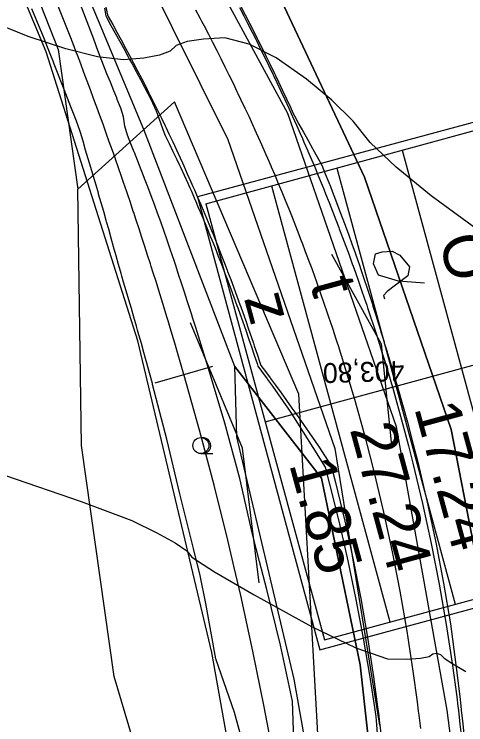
# Model space of a CAD drawing. Extents: x -574342 to -508101, y -1143544 to -1123894.
# Drawn here: x -508528.83 to -508506.16, y -1143313.1 to -1143277.46 of the extents above; entities that cross this region are included whole.
import ezdxf

# ---------------------------------------------------------------- set-up
doc = ezdxf.new("R2010")
doc.units = 0
for name, color, linetype in [('01_PARCELY_NAVRH_PC', 7, 'Continuous'), ('01_PARCELY_NAVRH_VHO', 7, 'Continuous'), ('01_PARCELY_NAVRH_ŽP', 7, 'Continuous'), ('1000', 7, 'Continuous'), ('21', 7, 'Continuous'), ('37', 7, 'Continuous'), ('42', 7, 'Continuous'), ('43', 7, 'Continuous'), ('6', 7, 'Continuous'), ('Level 255', 7, 'Continuous'), ('SO 101_popis oblouku', 7, 'Continuous'), ('tab', 7, 'Continuous'), ('VRST VEDL', 7, 'Continuous')]:
    doc.layers.add(name, color=color, linetype=linetype)

msp = doc.modelspace()

# ---------------------------------------------------------------- linework, layer by layer
msp.add_lwpolyline([(-508519.625, -1143286.627), (-508513.495, -1143309.334), (-508492.475, -1143303.66), (-508498.604, -1143280.952)], close=True)
at = {"layer": '01_PARCELY_NAVRH_PC'}
for points in [[(-508491.36, -1143454.58), (-508498.26, -1143372.94), (-508504.21, -1143312.1), (-508506.89, -1143298.29), (-508511.25, -1143285.64), (-508519.86, -1143267.33), (-508524.26, -1143263.08), (-508531.16, -1143250.06)], [(-508491.36, -1143454.58), (-508498.26, -1143372.94), (-508504.21, -1143312.1), (-508506.89, -1143298.29), (-508511.25, -1143285.64), (-508519.86, -1143267.33), (-508524.26, -1143263.08), (-508531.16, -1143250.06)], [(-508534.5, -1143254.93), (-508531.94, -1143260.32), (-508524.61, -1143277.77), (-508522.34, -1143283.22), (-508517.78, -1143295.12), (-508513.41, -1143300.73), (-508511.47, -1143310.09), (-508503.21, -1143384.65), (-508499.31, -1143428.14)], [(-508534.5, -1143254.93), (-508531.94, -1143260.32), (-508524.61, -1143277.77), (-508522.34, -1143283.22), (-508517.78, -1143295.12), (-508513.41, -1143300.73), (-508511.47, -1143310.09), (-508503.21, -1143384.65), (-508499.31, -1143428.14)]]:
    msp.add_lwpolyline(points, dxfattribs=at)
at = {"layer": '01_PARCELY_NAVRH_VHO'}
msp.add_lwpolyline([(-508497.13, -1143495.86), (-508497.34, -1143500.64), (-508499.94, -1143496.07), (-508501.52, -1143472.9), (-508509.71, -1143373.98), (-508513.61, -1143343.97), (-508516.21, -1143324.53), (-508518.91, -1143309.47), (-508522.63, -1143293.85), (-508527.23, -1143279.34), (-508534.32, -1143262.4), (-508535.36, -1143259.89), (-508531.94, -1143260.32), (-508524.61, -1143277.77), (-508522.34, -1143283.22), (-508517.78, -1143295.12), (-508517.67, -1143298.65), (-508514.79, -1143310.81), (-508512.2, -1143325.42), (-508505.85, -1143384.53), (-508502.4, -1143424.77), (-508500.25, -1143457.08), (-508499.28, -1143468.17)], close=True, dxfattribs=at)
msp.add_lwpolyline([(-508497.13, -1143495.86), (-508497.34, -1143500.64), (-508499.94, -1143496.07), (-508501.52, -1143472.9), (-508509.71, -1143373.98), (-508513.61, -1143343.97), (-508516.21, -1143324.53), (-508518.91, -1143309.47), (-508522.63, -1143293.85), (-508527.23, -1143279.34), (-508534.32, -1143262.4), (-508535.36, -1143259.89), (-508531.94, -1143260.32), (-508524.61, -1143277.77), (-508522.34, -1143283.22), (-508517.78, -1143295.12), (-508517.67, -1143298.65), (-508514.79, -1143310.81), (-508512.2, -1143325.42), (-508505.85, -1143384.53), (-508502.4, -1143424.77), (-508500.25, -1143457.08), (-508499.28, -1143468.17)], close=True, dxfattribs=at)
at = {"layer": '01_PARCELY_NAVRH_ŽP'}
for points in [[(-508425.23, -1143400.39), (-508448.26, -1143343.08), (-508432.21, -1143324.29), (-508434.31, -1143320.59), (-508441.9, -1143297.61), (-508445.4, -1143275.01), (-508446.02, -1143260.22), (-508475.11, -1143263.39), (-508493.5, -1143263.3), (-508514.56, -1143259.91), (-508521.01, -1143259.29), (-508524.26, -1143263.08), (-508519.86, -1143267.33), (-508511.25, -1143285.64), (-508506.89, -1143298.29), (-508504.21, -1143312.1), (-508498.26, -1143372.94), (-508491.36, -1143454.58)], [(-508493.822, -1143536.058), (-508493.49, -1143517.55), (-508493.74, -1143496.02), (-508496.01, -1143459.9), (-508497.29, -1143445.8), (-508499.31, -1143428.14), (-508503.21, -1143384.65), (-508511.47, -1143310.09), (-508513.41, -1143300.73), (-508517.78, -1143295.12), (-508517.67, -1143298.65), (-508514.79, -1143310.81), (-508512.2, -1143325.42), (-508505.85, -1143384.53), (-508502.4, -1143424.77), (-508500.25, -1143457.08), (-508499.28, -1143468.17), (-508497.13, -1143495.86), (-508497.34, -1143500.64), (-508498.93, -1143536.058)]]:
    msp.add_lwpolyline(points, dxfattribs=at)
at = {"layer": '1000'}
for points in [[(-508514.755, -1143314.812), (-508514.869, -1143311.915), (-508515.463, -1143309.107), (-508516.152, -1143306.32), (-508516.515, -1143304.909), (-508516.875, -1143303.544), (-508517.501, -1143300.743), (-508518.265, -1143297.978), (-508519.083, -1143295.228), (-508519.097, -1143295.183), (-508519.581, -1143293.612), (-508519.72, -1143293.168), (-508519.86, -1143292.725), (-508519.934, -1143292.49), (-508520.001, -1143292.281), (-508520.143, -1143291.838), (-508520.287, -1143291.396), (-508520.431, -1143290.954), (-508520.576, -1143290.512), (-508520.723, -1143290.071), (-508520.825, -1143289.765), (-508520.871, -1143289.63), (-508521.019, -1143289.189), (-508521.169, -1143288.749), (-508521.32, -1143288.309), (-508521.472, -1143287.869), (-508521.631, -1143287.432), (-508521.771, -1143287.058), (-508521.795, -1143286.997), (-508521.959, -1143286.562), (-508522.125, -1143286.127), (-508522.292, -1143285.693), (-508522.309, -1143285.65), (-508522.46, -1143285.259), (-508522.629, -1143284.826), (-508522.799, -1143284.393), (-508522.803, -1143284.383), (-508522.97, -1143283.961), (-508523.142, -1143283.529), (-508523.272, -1143283.082), (-508523.343, -1143282.614), (-508523.483, -1143282.17), (-508523.654, -1143281.738), (-508523.687, -1143281.657), (-508523.827, -1143281.306), (-508524.001, -1143280.875), (-508524.176, -1143280.444), (-508524.352, -1143280.014), (-508524.516, -1143279.579), (-508524.676, -1143279.142), (-508524.733, -1143278.989), (-508524.838, -1143278.707), (-508525.001, -1143278.271), (-508525.164, -1143277.836), (-508525.748, -1143276.31)], [(-508517.023, -1143315.225), (-508517.78, -1143312.488), (-508518.703, -1143309.793), (-508519.215, -1143307.014), (-508519.493, -1143305.606), (-508519.837, -1143304.259), (-508520.512, -1143301.516), (-508521.176, -1143298.77), (-508521.884, -1143296.033), (-508521.897, -1143295.988), (-508522.323, -1143294.425), (-508522.447, -1143293.983), (-508522.571, -1143293.542), (-508522.637, -1143293.308), (-508522.696, -1143293.101), (-508522.823, -1143292.66), (-508522.95, -1143292.219), (-508523.078, -1143291.779), (-508523.207, -1143291.338), (-508523.338, -1143290.899), (-508523.429, -1143290.593), (-508523.469, -1143290.459), (-508523.599, -1143290.019), (-508523.72, -1143289.576), (-508523.842, -1143289.133), (-508523.965, -1143288.69), (-508524.088, -1143288.248), (-508524.195, -1143287.868), (-508524.213, -1143287.806), (-508524.339, -1143287.364), (-508524.465, -1143286.922), (-508524.592, -1143286.48), (-508524.605, -1143286.437), (-508524.721, -1143286.039), (-508524.85, -1143285.598), (-508524.98, -1143285.157), (-508524.983, -1143285.146), (-508525.111, -1143284.716), (-508525.244, -1143284.275), (-508525.377, -1143283.835), (-508525.51, -1143283.395), (-508525.661, -1143282.961), (-508525.819, -1143282.529), (-508525.85, -1143282.449), (-508525.984, -1143282.1), (-508526.15, -1143281.672), (-508526.317, -1143281.243), (-508526.484, -1143280.816), (-508526.653, -1143280.388), (-508526.822, -1143279.961), (-508526.882, -1143279.811), (-508526.992, -1143279.534), (-508527.163, -1143279.108), (-508527.335, -1143278.682), (-508527.948, -1143277.187)], [(-508524.306, -1143277.155), (-508524.234, -1143277.541), (-508524.193, -1143277.617), (-508523.973, -1143278.021), (-508523.972, -1143278.023), (-508523.765, -1143278.409), (-508523.55, -1143278.794), (-508523.336, -1143279.18), (-508523.124, -1143279.566), (-508523.037, -1143279.726), (-508522.914, -1143279.953), (-508522.705, -1143280.341), (-508522.498, -1143280.731), (-508522.293, -1143281.121), (-508522.126, -1143281.443), (-508522.09, -1143281.512), (-508521.889, -1143281.904), (-508521.712, -1143282.309), (-508521.559, -1143282.724), (-508521.408, -1143283.14), (-508521.373, -1143283.238), (-508521.248, -1143283.552), (-508521.055, -1143283.947), (-508520.864, -1143284.344), (-508520.674, -1143284.742), (-508520.554, -1143284.998), (-508520.487, -1143285.14), (-508520.301, -1143285.539), (-508520.117, -1143285.939), (-508520.014, -1143286.17), (-508519.939, -1143286.342), (-508519.763, -1143286.746), (-508519.754, -1143286.767), (-508519.59, -1143287.15), (-508519.418, -1143287.556), (-508519.248, -1143287.962), (-508519.08, -1143288.369), (-508519.003, -1143288.558), (-508518.914, -1143288.777), (-508518.749, -1143289.185), (-508518.586, -1143289.594), (-508518.426, -1143290.004), (-508518.287, -1143290.363), (-508518.267, -1143290.415), (-508518.11, -1143290.826), (-508517.954, -1143291.239), (-508517.801, -1143291.651), (-508517.649, -1143292.065), (-508517.607, -1143292.182), (-508517.5, -1143292.479), (-508517.352, -1143292.894), (-508517.206, -1143293.309), (-508517.062, -1143293.726), (-508516.963, -1143294.014), (-508516.92, -1143294.142), (-508516.779, -1143294.56), (-508516.641, -1143294.978), (-508516.595, -1143295.119), (-508516.412, -1143295.367), (-508516.137, -1143295.743), (-508516.109, -1143295.781), (-508515.863, -1143296.12), (-508515.591, -1143296.5), (-508515.321, -1143296.881), (-508515.054, -1143297.265), (-508514.925, -1143297.464), (-508514.803, -1143297.655), (-508513.835, -1143299.2), (-508513.221, -1143300.185), (-508513, -1143301.025), (-508512.523, -1143302.946), (-508512.081, -1143304.876), (-508511.676, -1143306.815), (-508511.308, -1143308.761), (-508510.976, -1143310.715), (-508510.746, -1143312.227), (-508510.682, -1143312.676), (-508510.653, -1143312.879), (-508510.61, -1143313.536)], [(-508524.226, -1143277.11), (-508524.153, -1143277.496), (-508524.111, -1143277.572), (-508523.888, -1143277.973), (-508523.887, -1143277.975), (-508523.674, -1143278.36), (-508523.463, -1143278.747), (-508523.253, -1143279.135), (-508523.045, -1143279.524), (-508522.959, -1143279.685), (-508522.838, -1143279.913), (-508522.634, -1143280.304), (-508522.431, -1143280.696), (-508522.23, -1143281.089), (-508522.066, -1143281.413), (-508522.031, -1143281.482), (-508521.834, -1143281.877), (-508521.639, -1143282.272), (-508521.445, -1143282.669), (-508521.253, -1143283.066), (-508521.209, -1143283.159), (-508521.063, -1143283.464), (-508520.875, -1143283.863), (-508520.689, -1143284.263), (-508520.504, -1143284.664), (-508520.386, -1143284.922), (-508520.322, -1143285.065), (-508520.141, -1143285.467), (-508519.962, -1143285.871), (-508519.86, -1143286.103), (-508519.785, -1143286.275), (-508519.61, -1143286.679), (-508519.6, -1143286.701), (-508519.436, -1143287.085), (-508519.265, -1143287.492), (-508519.095, -1143287.899), (-508518.927, -1143288.307), (-508518.85, -1143288.496), (-508518.762, -1143288.715), (-508518.598, -1143289.125), (-508518.435, -1143289.535), (-508518.275, -1143289.946), (-508518.137, -1143290.305), (-508518.117, -1143290.358), (-508517.96, -1143290.77), (-508517.806, -1143291.183), (-508517.653, -1143291.597), (-508517.503, -1143292.012), (-508517.46, -1143292.129), (-508517.354, -1143292.427), (-508517.207, -1143292.843), (-508517.062, -1143293.26), (-508516.919, -1143293.677), (-508516.821, -1143293.966), (-508516.777, -1143294.095), (-508516.638, -1143294.513), (-508516.501, -1143294.932), (-508516.455, -1143295.074), (-508516.269, -1143295.321), (-508515.989, -1143295.696), (-508515.961, -1143295.735), (-508515.711, -1143296.073), (-508515.434, -1143296.452), (-508515.159, -1143296.833), (-508514.886, -1143297.215), (-508514.746, -1143297.412), (-508514.614, -1143297.6), (-508513.562, -1143299.126), (-508512.912, -1143300.105), (-508512.698, -1143300.949), (-508512.238, -1143302.881), (-508511.817, -1143304.821), (-508511.436, -1143306.77), (-508511.094, -1143308.726), (-508510.792, -1143310.689), (-508510.586, -1143312.207), (-508510.53, -1143312.657), (-508510.505, -1143312.861), (-508510.428, -1143313.516)], [(-508517.528, -1143277.12), (-508517.311, -1143277.535), (-508517.096, -1143277.951), (-508516.882, -1143278.369), (-508516.708, -1143278.713), (-508516.671, -1143278.787), (-508516.461, -1143279.206), (-508516.254, -1143279.626), (-508516.048, -1143280.047), (-508515.844, -1143280.47), (-508515.797, -1143280.568), (-508515.642, -1143280.892), (-508515.442, -1143281.316), (-508515.244, -1143281.741), (-508515.048, -1143282.167), (-508514.923, -1143282.441), (-508514.854, -1143282.594), (-508514.662, -1143283.021), (-508514.472, -1143283.449), (-508514.364, -1143283.696), (-508514.284, -1143283.879), (-508514.098, -1143284.309), (-508514.088, -1143284.332), (-508513.914, -1143284.74), (-508513.731, -1143285.172), (-508513.551, -1143285.604), (-508513.373, -1143286.038), (-508513.291, -1143286.239), (-508513.197, -1143286.472), (-508513.022, -1143286.907), (-508512.85, -1143287.343), (-508512.68, -1143287.78), (-508512.533, -1143288.161), (-508512.512, -1143288.217), (-508512.346, -1143288.655), (-508512.181, -1143289.094), (-508512.019, -1143289.534), (-508511.859, -1143289.974), (-508511.814, -1143290.099), (-508511.701, -1143290.416), (-508511.545, -1143290.858), (-508511.391, -1143291.3), (-508511.239, -1143291.743), (-508511.135, -1143292.051), (-508511.089, -1143292.188), (-508510.941, -1143292.632), (-508510.795, -1143293.078), (-508510.746, -1143293.228), (-508510.651, -1143293.524), (-508510.509, -1143293.97), (-508510.495, -1143294.016), (-508510.369, -1143294.418), (-508510.232, -1143294.866), (-508510.096, -1143295.314), (-508509.962, -1143295.764), (-508509.895, -1143295.994), (-508509.831, -1143296.213), (-508509.335, -1143297.983), (-508509.039, -1143299.104), (-508508.816, -1143299.983), (-508508.337, -1143301.994), (-508507.899, -1143304.014), (-508507.503, -1143306.042), (-508507.147, -1143308.078), (-508506.833, -1143310.121), (-508506.619, -1143311.701), (-508506.56, -1143312.169), (-508506.534, -1143312.382), (-508506.454, -1143313.063), (-508506.379, -1143313.744)], [(-508517.456, -1143277.082), (-508517.238, -1143277.497), (-508517.021, -1143277.913), (-508516.806, -1143278.33), (-508516.631, -1143278.675), (-508516.594, -1143278.748), (-508516.383, -1143279.168), (-508516.175, -1143279.588), (-508515.969, -1143280.009), (-508515.764, -1143280.431), (-508515.717, -1143280.53), (-508515.562, -1143280.854), (-508515.362, -1143281.279), (-508515.164, -1143281.704), (-508514.967, -1143282.13), (-508514.841, -1143282.404), (-508514.766, -1143282.554), (-508514.548, -1143282.97), (-508514.314, -1143283.38), (-508514.18, -1143283.615), (-508514.081, -1143283.79), (-508513.85, -1143284.202), (-508513.837, -1143284.224), (-508513.62, -1143284.615), (-508513.392, -1143285.029), (-508513.213, -1143285.464), (-508513.038, -1143285.901), (-508512.958, -1143286.104), (-508512.866, -1143286.339), (-508512.696, -1143286.777), (-508512.527, -1143287.216), (-508512.361, -1143287.656), (-508512.217, -1143288.041), (-508512.196, -1143288.097), (-508512.035, -1143288.538), (-508511.876, -1143288.981), (-508511.72, -1143289.424), (-508511.565, -1143289.868), (-508511.522, -1143289.994), (-508511.413, -1143290.313), (-508511.263, -1143290.759), (-508511.114, -1143291.205), (-508510.968, -1143291.651), (-508510.868, -1143291.961), (-508510.824, -1143292.099), (-508510.681, -1143292.547), (-508510.541, -1143292.995), (-508510.494, -1143293.147), (-508510.403, -1143293.444), (-508510.267, -1143293.894), (-508510.253, -1143293.94), (-508510.133, -1143294.344), (-508509.994, -1143294.793), (-508509.858, -1143295.243), (-508509.723, -1143295.693), (-508509.656, -1143295.924), (-508509.591, -1143296.144), (-508509.096, -1143297.918), (-508508.797, -1143299.042), (-508508.573, -1143299.923), (-508508.094, -1143301.939), (-508507.661, -1143303.965), (-508507.274, -1143306), (-508506.937, -1143308.043), (-508506.656, -1143310.095), (-508506.469, -1143311.682), (-508506.419, -1143312.152), (-508506.396, -1143312.365), (-508506.316, -1143313.047), (-508506.241, -1143313.73)]]:
    msp.add_lwpolyline(points, dxfattribs=at)
at = {"layer": '21'}
for points in [[(-508515.752, -1143314.994), (-508516.282, -1143312.193), (-508516.852, -1143309.401), (-508517.462, -1143306.617), (-508517.787, -1143305.207), (-508518.112, -1143303.842), (-508518.801, -1143301.077), (-508519.529, -1143298.322), (-508520.296, -1143295.577), (-508520.309, -1143295.531), (-508520.767, -1143293.964), (-508520.899, -1143293.521), (-508521.032, -1143293.078), (-508521.102, -1143292.844), (-508521.166, -1143292.635), (-508521.301, -1143292.193), (-508521.437, -1143291.751), (-508521.574, -1143291.31), (-508521.712, -1143290.869), (-508521.851, -1143290.428), (-508521.948, -1143290.122), (-508521.991, -1143289.987), (-508522.132, -1143289.547), (-508522.274, -1143289.107), (-508522.417, -1143288.667), (-508522.561, -1143288.228), (-508522.706, -1143287.789), (-508522.832, -1143287.413), (-508522.852, -1143287.351), (-508523, -1143286.912), (-508523.148, -1143286.474), (-508523.297, -1143286.037), (-508523.312, -1143285.994), (-508523.447, -1143285.6), (-508523.598, -1143285.163), (-508523.751, -1143284.726), (-508523.754, -1143284.716), (-508523.904, -1143284.29), (-508524.058, -1143283.854), (-508524.213, -1143283.419), (-508524.37, -1143282.984), (-508524.527, -1143282.549), (-508524.685, -1143282.115), (-508524.715, -1143282.033), (-508524.845, -1143281.681), (-508525.005, -1143281.247), (-508525.166, -1143280.814), (-508525.328, -1143280.381), (-508525.492, -1143279.948), (-508525.656, -1143279.516), (-508525.714, -1143279.364), (-508525.821, -1143279.084), (-508525.987, -1143278.653), (-508526.155, -1143278.222), (-508526.751, -1143276.709)], [(-508519.73, -1143277.24), (-508519.513, -1143277.645), (-508519.424, -1143277.813), (-508519.298, -1143278.051), (-508519.085, -1143278.458), (-508518.874, -1143278.866), (-508518.665, -1143279.275), (-508518.494, -1143279.613), (-508518.458, -1143279.685), (-508518.252, -1143280.096), (-508518.049, -1143280.508), (-508517.847, -1143280.921), (-508517.647, -1143281.335), (-508517.601, -1143281.432), (-508517.449, -1143281.75), (-508517.253, -1143282.165), (-508517.059, -1143282.582), (-508516.867, -1143282.999), (-508516.744, -1143283.268), (-508516.677, -1143283.417), (-508516.488, -1143283.837), (-508516.302, -1143284.257), (-508516.196, -1143284.498), (-508516.118, -1143284.677), (-508515.935, -1143285.099), (-508515.925, -1143285.122), (-508515.754, -1143285.522), (-508515.576, -1143285.945), (-508515.399, -1143286.369), (-508515.224, -1143286.794), (-508515.144, -1143286.991), (-508515.052, -1143287.22), (-508514.881, -1143287.646), (-508514.712, -1143288.074), (-508514.545, -1143288.502), (-508514.401, -1143288.876), (-508514.38, -1143288.931), (-508514.217, -1143289.36), (-508514.056, -1143289.791), (-508513.897, -1143290.222), (-508513.74, -1143290.654), (-508513.696, -1143290.776), (-508513.585, -1143291.086), (-508513.432, -1143291.519), (-508513.281, -1143291.953), (-508513.132, -1143292.388), (-508513.03, -1143292.689), (-508512.985, -1143292.823), (-508512.84, -1143293.259), (-508512.697, -1143293.696), (-508512.649, -1143293.844), (-508512.556, -1143294.133), (-508512.417, -1143294.571), (-508512.403, -1143294.616), (-508512.28, -1143295.01), (-508512.145, -1143295.449), (-508512.012, -1143295.889), (-508511.881, -1143296.329), (-508511.815, -1143296.555), (-508511.752, -1143296.77), (-508511.266, -1143298.505), (-508510.975, -1143299.604), (-508510.757, -1143300.466), (-508510.287, -1143302.437), (-508509.858, -1143304.418), (-508509.469, -1143306.406), (-508509.121, -1143308.402), (-508508.812, -1143310.405), (-508508.602, -1143311.954), (-508508.545, -1143312.413), (-508508.52, -1143312.621), (-508508.441, -1143313.289)]]:
    msp.add_lwpolyline(points, dxfattribs=at)
at = {"layer": '37'}
for points in [[(-508544.44, -1143182.59), (-508545.29, -1143193.14), (-508544.8, -1143205.6), (-508541.6, -1143228.19), (-508538.07, -1143243), (-508531.89, -1143258.66), (-508522.3, -1143275.29), (-508518.1, -1143283.75), (-508512.73, -1143299.25), (-508510.49, -1143313.12)], [(-508544.44, -1143182.59), (-508545.29, -1143193.14), (-508544.8, -1143205.6), (-508541.6, -1143228.19), (-508538.07, -1143243), (-508531.89, -1143258.66), (-508522.3, -1143275.29), (-508518.1, -1143283.75), (-508512.73, -1143299.25), (-508510.49, -1143313.12)], [(-508507.09, -1143312.37), (-508509.64, -1143298.16), (-508515.1, -1143282.44), (-508519.8, -1143273.76), (-508526.92, -1143261.04), (-508530.09, -1143253.58), (-508534.91, -1143241.83), (-508538.52, -1143226.92), (-508541.3, -1143204.98), (-508541.88, -1143193.39), (-508540.68, -1143183.59)], [(-508507.09, -1143312.37), (-508509.64, -1143298.16), (-508515.1, -1143282.44), (-508519.8, -1143273.76), (-508526.92, -1143261.04), (-508530.09, -1143253.58), (-508534.91, -1143241.83), (-508538.52, -1143226.92), (-508541.3, -1143204.98), (-508541.88, -1143193.39), (-508540.68, -1143183.59)], [(-508489.812, -1143536.058), (-508489.7, -1143532.61), (-508489.43, -1143504.5), (-508490.15, -1143484.79), (-508492.11, -1143459.13), (-508495.1, -1143425.66), (-508500.09, -1143376.04), (-508503.8, -1143337.81), (-508507.09, -1143312.37)], [(-508489.812, -1143536.058), (-508489.7, -1143532.61), (-508489.43, -1143504.5), (-508490.15, -1143484.79), (-508492.11, -1143459.13), (-508495.1, -1143425.66), (-508500.09, -1143376.04), (-508503.8, -1143337.81), (-508507.09, -1143312.37)]]:
    msp.add_lwpolyline(points, dxfattribs=at)
at = {"layer": '42'}
for points in [[(-508654.2, -1143191.6), (-508651.11, -1143191.46), (-508646.05, -1143192.58), (-508613.56, -1143216.76), (-508566.08, -1143248.87), (-508547.92, -1143260.05), (-508536.29, -1143266.06), (-508529.87, -1143271.02), (-508526.62, -1143279.23), (-508525.63, -1143286.24)], [(-508654.2, -1143191.6), (-508651.11, -1143191.46), (-508646.05, -1143192.58), (-508613.56, -1143216.76), (-508566.08, -1143248.87), (-508547.92, -1143260.05), (-508536.29, -1143266.06), (-508529.87, -1143271.02), (-508526.62, -1143279.23), (-508525.63, -1143286.24)], [(-508495.7, -1143263.7), (-508516.42, -1143260.79), (-508519.86, -1143267.33), (-508511.25, -1143285.64), (-508506.89, -1143298.29), (-508504.21, -1143312.1)], [(-508495.7, -1143263.7), (-508516.42, -1143260.79), (-508519.86, -1143267.33), (-508511.25, -1143285.64), (-508506.89, -1143298.29), (-508504.21, -1143312.1)], [(-508513.4, -1143316.85), (-508514.55, -1143296.52), (-508520.78, -1143281.86), (-508525.63, -1143286.24)], [(-508513.4, -1143316.85), (-508514.55, -1143296.52), (-508520.78, -1143281.86), (-508525.63, -1143286.24)], [(-508513.4, -1143316.85), (-508521.01, -1143320.13), (-508523.81, -1143310.68), (-508525.45, -1143299.09), (-508525.63, -1143286.24)], [(-508513.4, -1143316.85), (-508521.01, -1143320.13), (-508523.81, -1143310.68), (-508525.45, -1143299.09), (-508525.63, -1143286.24)]]:
    msp.add_lwpolyline(points, dxfattribs=at)
at = {"layer": '43'}
for p, q in [((-508519.461, -1143299.495), (-508519.361, -1143299.495)), ((-508519.361, -1143299.495), (-508518.861, -1143299.495))]:
    msp.add_line(p, q, dxfattribs=at)
msp.add_circle((-508519.461, -1143299.095), 0.4, dxfattribs=at)
msp.add_arc((-508519.361, -1143299.095), 0.4, 259.6952, 97.1808, dxfattribs=at)
at = {"layer": '6'}
for points in [[(-508521.751, -1143295.946), (-508518.868, -1143295.117)], [(-508520.309, -1143295.531), (-508520.309, -1143295.531)]]:
    msp.add_lwpolyline(points, dxfattribs=at)
at = {"layer": 'SO 101_popis oblouku'}
for p, q in [((-508519.204, -1143286.964), (-508502.801, -1143282.499)), ((-508509.362, -1143284.285), (-508503.409, -1143306.156)), ((-508512.643, -1143285.178), (-508506.689, -1143307.049)), ((-508515.923, -1143286.071), (-508509.97, -1143307.942)), ((-508519.204, -1143286.964), (-508513.251, -1143308.835)), ((-508516.227, -1143297.899), (-508499.824, -1143293.434)), ((-508513.251, -1143308.835), (-508496.847, -1143304.37))]:
    msp.add_line(p, q, dxfattribs=at)
msp.add_lwpolyline([(-508508.229, -1143290.948), (-508509.544, -1143290.855), (-508510.536, -1143290.556), (-508510.794, -1143289.978), (-508510.686, -1143289.476), (-508510.366, -1143289.382), (-508509.851, -1143289.345), (-508509.476, -1143289.55), (-508508.993, -1143290.134), (-508509.07, -1143290.58), (-508509.692, -1143291.053), (-508510.112, -1143291.36), (-508510.29, -1143291.563), (-508510.242, -1143291.739)], dxfattribs=at)
at = {"layer": 'tab'}
for points in [[(-508512.905, -1143289.5), (-508510.41, -1143293.989), (-508509.887, -1143299.099)], [(-508516.539, -1143305.985), (-508517.374, -1143299.226), (-508519.987, -1143292.937)]]:
    msp.add_lwpolyline(points, dxfattribs=at)
at = {"layer": 'VRST VEDL'}
for points in [[(-508505.664, -1143288.205), (-508507.892, -1143286.577), (-508509.659, -1143285.137), (-508510.966, -1143283.888), (-508511.813, -1143282.827), (-508512.88, -1143281.768), (-508514.166, -1143280.711), (-508515.673, -1143279.656), (-508517.035, -1143278.97), (-508518.254, -1143278.653), (-508519.329, -1143278.706), (-508520.146, -1143278.832), (-508520.705, -1143279.034), (-508521.006, -1143279.31), (-508521.544, -1143279.521), (-508522.321, -1143279.668), (-508523.337, -1143279.751), (-508524.643, -1143279.596), (-508526.24, -1143279.204), (-508528.128, -1143278.575), (-508530.201, -1143277.747)], [(-508529.261, -1143300.599), (-508525.463, -1143301.902), (-508522.933, -1143302.857), (-508521.669, -1143303.464), (-508520.744, -1143303.972), (-508520.157, -1143304.381), (-508519.908, -1143304.69), (-508518.783, -1143305.426), (-508516.783, -1143306.588), (-508513.907, -1143308.178), (-508511.674, -1143309.243), (-508510.084, -1143309.784), (-508509.136, -1143309.8), (-508508.441, -1143309.763), (-508508, -1143309.675), (-508507.812, -1143309.534), (-508507.624, -1143309.502), (-508507.435, -1143309.578), (-508507.245, -1143309.764), (-508506.819, -1143310.045), (-508506.155, -1143310.42)]]:
    msp.add_lwpolyline(points, dxfattribs=at)

# ---------------------------------------------------------------- texts
at = {"layer": 'Level 255'}
msp.add_text('403,80', height=1, rotation=181.6706, dxfattribs=at).set_placement((-508509.26, -1143294.847))
at = {"layer": 'SO 101_popis oblouku'}
for s, height, p in [('O', 2.267, (-508507.533, -1143288.765)), ('t', 2.267, (-508513.981, -1143290.967)), ('z', 2.267, (-508517.304, -1143291.704)), ('17.24', 2.2667, (-508508.76, -1143297.202)), ('27.24', 2.2667, (-508511.993, -1143298.27)), ('1.85', 2.2667, (-508515.039, -1143300.022))]:
    msp.add_text(s, height=height, rotation=285.222, dxfattribs=at).set_placement(p)

doc.saveas('drawing.dxf')
